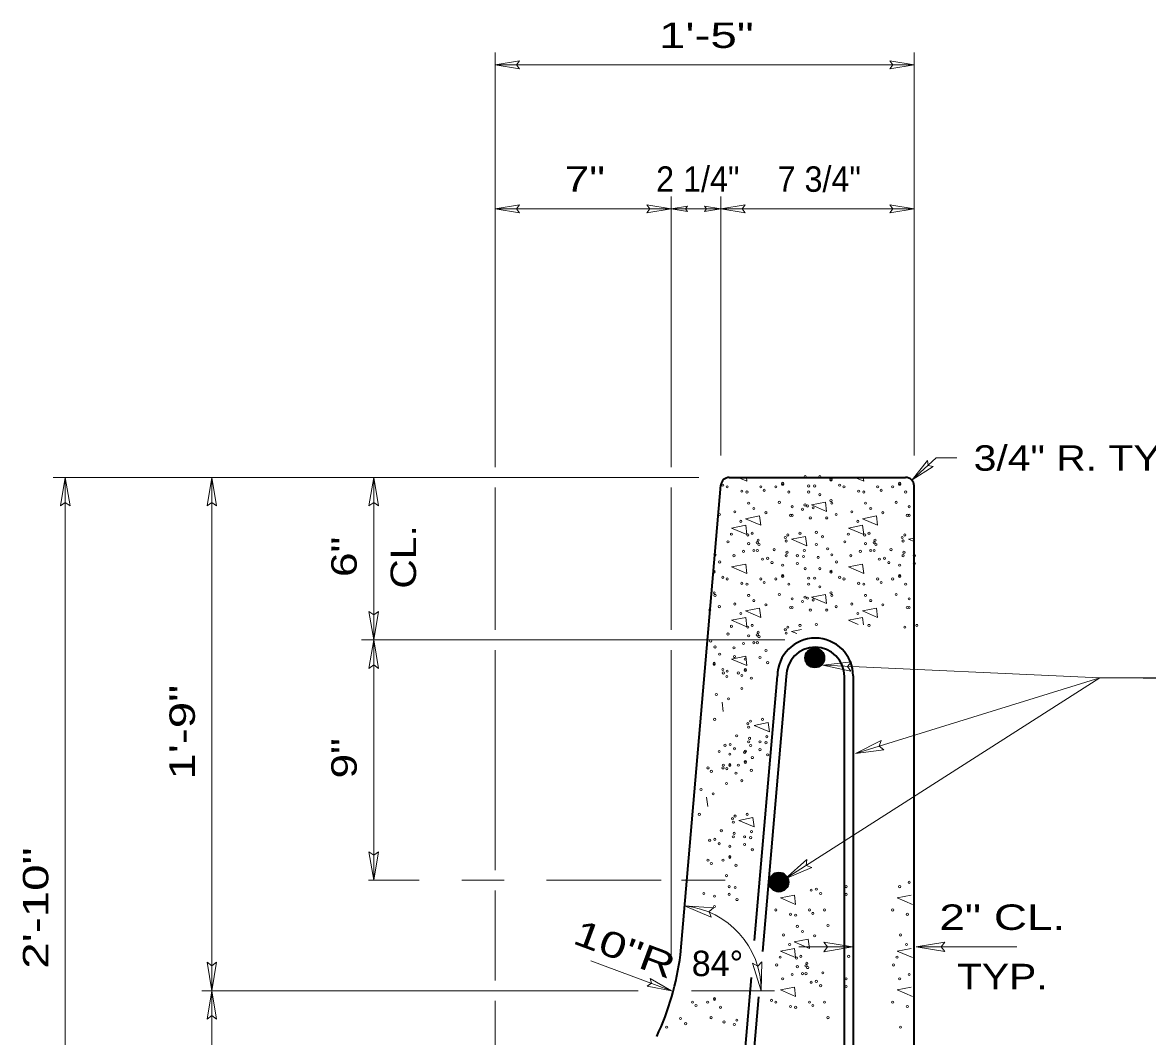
# Model space of a CAD drawing. Extents: x 2.21 to 9.21, y 11.59 to 21.05.
# Drawn here: x 2.823 to 5.477, y 18.662 to 21.053 of the extents above; entities that cross this region are included whole.
import ezdxf
from ezdxf.enums import TextEntityAlignment as Align

# ---------------------------------------------------------------- set-up
doc = ezdxf.new("R2010")
doc.units = 0
doc.header["$LTSCALE"] = 0.024
doc.linetypes.add('DOT_DASHED', pattern=[7.7, 5, -1.2, 0.3, -1.2])
for name, color, linetype, lineweight in [('1', 7, 'Continuous', 35), ('10', 7, 'Continuous', 13), ('12', 7, 'Continuous', 53), ('6', 7, 'Continuous', 13)]:
    doc.layers.add(name, color=color, linetype=linetype, lineweight=lineweight)

msp = doc.modelspace()

# ---------------------------------------------------------------- linework, layer by layer
at = {"layer": '1'}
for p, q in [((4.3755, 18.85467), (4.47067, 19.962)), ((4.49067, 19.98033), (4.9065, 19.98033)), ((4.92667, 17.90333), (4.92667, 19.96033)), ((4.55033, 18.88833), (4.604, 19.512)), ((4.62467, 19.51117), (4.56883, 18.86217))]:
    msp.add_line(p, q, dxfattribs=at)
for points in [[(4.78283, 19.512), (4.78283, 17.57083), (4.78283, 17.57), (4.76217, 17.57), (4.76217, 19.51117)], [(4.5595, 18.755), (4.48883, 17.93367), (4.48883, 17.56383), (4.48883, 17.5645), (4.46833, 17.5645), (4.46833, 17.93417), (4.54283, 18.80083)]]:
    msp.add_lwpolyline(points, dxfattribs=at)
for centre, radius in [((4.69223, 19.55451), 0.02253), ((4.69204, 19.5547), 0.02103), ((4.69002, 19.5547), 0.01823), ((4.69229, 19.55417), 0.02028), ((4.69289, 19.55321), 0.01988), ((4.69278, 19.55392), 0.0185), ((4.69076, 19.55559), 0.01508), ((4.69328, 19.55381), 0.01751), ((4.69342, 19.55332), 0.0166), ((4.69041, 19.55381), 0.01309), ((4.69367, 19.55307), 0.01584), ((4.69342, 19.55268), 0.0151), ((4.68927, 19.55307), 0.01045), ((4.69381, 19.55268), 0.01471), ((4.69353, 19.55293), 0.01421), ((4.69416, 19.55257), 0.01358), ((4.6943, 19.55282), 0.01272), ((4.69441, 19.55296), 0.01184), ((4.69101, 19.55357), 0.00844), ((4.69441, 19.55321), 0.01085), ((4.69455, 19.55293), 0.01021), ((4.69455, 19.55282), 0.00921), ((4.69494, 19.55204), 0.00882), ((4.69516, 19.55194), 0.00805), ((4.69516, 19.55215), 0.00706), ((4.69544, 19.55233), 0.00681), ((4.69544, 19.55169), 0.00627), ((4.69569, 19.55218), 0.00602), ((4.69579, 19.55204), 0.00515), ((4.69544, 19.55243), 0.0043), ((4.69594, 19.5519), 0.00382), ((4.69608, 19.55194), 0.00316), ((4.69632, 19.55179), 0.00241), ((4.69632, 19.55204), 0.00213), ((4.69707, 19.55194), 0.00267), ((4.69629, 19.55204), 0.00139), ((4.69604, 19.55204), 0.000653), ((4.69657, 19.55204), 0.000415), ((4.60766, 19.02591), 0.02253), ((4.60746, 19.0261), 0.02103), ((4.60544, 19.0261), 0.01823), ((4.60771, 19.02556), 0.02028), ((4.60831, 19.02461), 0.01988), ((4.60821, 19.02532), 0.0185), ((4.60619, 19.02698), 0.01508), ((4.6087, 19.02521), 0.01751), ((4.60885, 19.02471), 0.0166), ((4.60583, 19.02521), 0.01309), ((4.60909, 19.02447), 0.01584), ((4.60885, 19.02408), 0.0151), ((4.6047, 19.02447), 0.01045), ((4.60924, 19.02408), 0.01471), ((4.60895, 19.02432), 0.01421), ((4.60959, 19.02397), 0.01358), ((4.60973, 19.02422), 0.01272), ((4.60984, 19.02436), 0.01184), ((4.60644, 19.02496), 0.00844), ((4.60984, 19.02461), 0.01085), ((4.60998, 19.02432), 0.01021), ((4.60998, 19.02422), 0.00921), ((4.61037, 19.02344), 0.00882), ((4.61058, 19.02333), 0.00805), ((4.61058, 19.02354), 0.00706), ((4.61087, 19.02372), 0.00681), ((4.61087, 19.02308), 0.00627), ((4.61111, 19.02358), 0.00602), ((4.61122, 19.02344), 0.00515), ((4.61087, 19.02383), 0.0043), ((4.61136, 19.0233), 0.00382), ((4.6115, 19.02333), 0.00316), ((4.61175, 19.02319), 0.00241), ((4.61175, 19.02344), 0.00213), ((4.6125, 19.02333), 0.00267), ((4.61172, 19.02344), 0.00139), ((4.61147, 19.02344), 0.000653), ((4.612, 19.02344), 0.000415)]:
    msp.add_circle(centre, radius, dxfattribs=at)
for centre, radius, start, end in [((4.49063, 19.96026), 0.02, 90, 175.08387), ((4.90658, 19.96026), 0.02, 0, 90), ((4.69339, 19.512), 0.08937, 0, 180), ((4.69339, 19.51114), 0.06877, 0, 180), ((3.72781, 18.93854), 0.65305, 334.93556, 352.62166)]:
    msp.add_arc(centre, radius, start, end, dxfattribs=at)
at = {"layer": '10'}
for p, q in [((3.938, 20.00433), (3.938, 20.982)), ((4.92667, 20.03233), (4.92667, 20.982)), ((3.99567, 20.96267), (3.938, 20.95317)), ((3.938, 20.95317), (4.92667, 20.95317)), ((3.99567, 20.9435), (3.938, 20.95317)), ((3.99567, 20.96267), (3.9885, 20.95317)), ((3.99567, 20.9435), (3.9885, 20.95317)), ((4.869, 20.96267), (4.92667, 20.95317)), ((4.869, 20.96267), (4.87617, 20.95317)), ((4.869, 20.9435), (4.92667, 20.95317)), ((4.869, 20.9435), (4.87617, 20.95317)), ((3.99567, 20.6235), (3.938, 20.61383)), ((3.99567, 20.6235), (3.9885, 20.61383)), ((4.29583, 20.6235), (4.3535, 20.61383)), ((4.29583, 20.6235), (4.303, 20.61383)), ((4.3535, 20.64267), (4.3535, 20.00433)), ((4.47067, 20.03233), (4.47067, 20.64267)), ((4.52833, 20.6235), (4.47067, 20.61383)), ((4.52833, 20.6235), (4.52117, 20.61383)), ((4.869, 20.6235), (4.92667, 20.61383)), ((4.869, 20.6235), (4.87617, 20.61383)), ((3.99567, 20.60417), (3.938, 20.61383)), ((3.99567, 20.60417), (3.9885, 20.61383)), ((4.29583, 20.60417), (4.3535, 20.61383)), ((4.29583, 20.60417), (4.303, 20.61383)), ((4.39183, 20.62017), (4.3535, 20.61383)), ((4.39183, 20.6075), (4.3535, 20.61383)), ((4.39183, 20.62017), (4.387, 20.61383)), ((4.39183, 20.6075), (4.387, 20.61383)), ((4.43233, 20.62017), (4.47067, 20.61383)), ((4.43233, 20.62017), (4.43717, 20.61383)), ((4.43233, 20.6075), (4.47067, 20.61383)), ((4.43233, 20.6075), (4.43717, 20.61383)), ((4.52833, 20.60417), (4.47067, 20.61383)), ((4.52833, 20.60417), (4.52117, 20.61383)), ((4.869, 20.60417), (4.92667, 20.61383)), ((4.869, 20.60417), (4.87617, 20.61383)), ((4.95833, 20.02033), (4.92217, 19.9745)), ((4.95833, 20.02033), (4.9595, 20.00833)), ((4.97133, 20.00617), (4.92217, 19.9745)), ((4.97133, 20.00617), (4.9595, 20.00833)), ((4.41867, 19.98033), (2.89533, 19.98033)), ((2.91283, 19.913), (2.924, 19.98033)), ((2.924, 17.9405), (2.924, 19.98033)), ((2.93533, 19.913), (2.924, 19.98033)), ((3.25867, 19.913), (3.26983, 19.98033)), ((3.281, 19.913), (3.26983, 19.98033)), ((3.26983, 18.76983), (3.26983, 19.98033)), ((3.6405, 19.913), (3.65167, 19.98033)), ((3.66283, 19.913), (3.65167, 19.98033)), ((3.65167, 19.59717), (3.65167, 19.98033)), ((3.938, 19.62117), (3.938, 19.95633)), ((4.3535, 19.95633), (4.3535, 19.62117)), ((2.91283, 19.913), (2.924, 19.9215)), ((2.93533, 19.913), (2.924, 19.9215)), ((3.25867, 19.913), (3.26983, 19.9215)), ((3.281, 19.913), (3.26983, 19.9215)), ((3.6405, 19.913), (3.65167, 19.9215)), ((3.66283, 19.913), (3.65167, 19.9215)), ((3.6405, 19.66433), (3.65167, 19.59717)), ((3.6405, 19.66433), (3.65167, 19.656)), ((3.66283, 19.66433), (3.65167, 19.59717)), ((3.66283, 19.66433), (3.65167, 19.656)), ((4.62133, 19.59717), (3.62283, 19.59717)), ((3.6405, 19.53), (3.65167, 19.59717)), ((3.65167, 19.03033), (3.65167, 19.59717)), ((3.66283, 19.53), (3.65167, 19.59717)), ((3.938, 19.05433), (3.938, 19.57317)), ((4.3535, 18.85217), (4.3535, 19.57317)), ((3.6405, 19.53), (3.65167, 19.53833)), ((3.66283, 19.53), (3.65167, 19.53833)), ((4.77867, 19.5455), (4.711, 19.53733)), ((5.36517, 19.5075), (4.711, 19.53733)), ((4.77767, 19.52317), (4.711, 19.53733)), ((4.77867, 19.5455), (4.76983, 19.53467)), ((4.77767, 19.52317), (4.76983, 19.53467)), ((5.36517, 19.5075), (4.62267, 19.03333)), ((5.36517, 19.5075), (4.788, 19.329)), ((5.46717, 19.5075), (5.36517, 19.5075)), ((4.84883, 19.35967), (4.788, 19.329)), ((4.84883, 19.35967), (4.84417, 19.3465)), ((4.8555, 19.33817), (4.788, 19.329)), ((4.8555, 19.33817), (4.84417, 19.3465)), ((3.6405, 19.0975), (3.65167, 19.03033)), ((3.6405, 19.0975), (3.65167, 19.08917)), ((3.66283, 19.0975), (3.65167, 19.03033)), ((3.66283, 19.0975), (3.65167, 19.08917)), ((4.67333, 19.079), (4.62267, 19.03333)), ((4.68533, 19.06017), (4.62267, 19.03333)), ((4.67333, 19.079), (4.67233, 19.065)), ((4.68533, 19.06017), (4.67233, 19.065)), ((3.938, 18.79383), (3.938, 19.00633)), ((4.17933, 19.03033), (4.3295, 19.03033)), ((4.4805, 19.03033), (4.3775, 19.03033)), ((4.44817, 18.94333), (4.38533, 18.96983)), ((4.45367, 18.965), (4.38533, 18.96983)), ((4.45367, 18.965), (4.44317, 18.95633)), ((4.44817, 18.94333), (4.44317, 18.95633)), ((4.65483, 18.873), (4.781, 18.873)), ((4.71383, 18.88433), (4.781, 18.873)), ((4.71383, 18.88433), (4.72233, 18.873)), ((4.71383, 18.86183), (4.781, 18.873)), ((4.71383, 18.86183), (4.72233, 18.873)), ((4.999, 18.8845), (4.93183, 18.87333)), ((5.16917, 18.87333), (4.93183, 18.87333)), ((4.999, 18.86217), (4.93183, 18.87333)), ((4.999, 18.8845), (4.99067, 18.87333)), ((4.999, 18.86217), (4.99067, 18.87333)), ((3.25867, 18.837), (3.26983, 18.76983)), ((3.25867, 18.837), (3.26983, 18.82867)), ((3.281, 18.837), (3.26983, 18.76983)), ((3.281, 18.837), (3.26983, 18.82867)), ((4.35433, 18.76983), (4.164, 18.8405)), ((4.54533, 18.83483), (4.56583, 18.76983)), ((4.54533, 18.83483), (4.55767, 18.828)), ((4.5675, 18.838), (4.55767, 18.828)), ((4.5675, 18.838), (4.56583, 18.76983)), ((4.30367, 18.79883), (4.35433, 18.76983)), ((4.30367, 18.79883), (4.30717, 18.78733)), ((4.276, 18.76983), (3.24583, 18.76983)), ((3.25867, 18.7025), (3.26983, 18.76983)), ((3.281, 18.7025), (3.26983, 18.76983)), ((4.297, 18.78083), (4.30717, 18.78733)), ((4.297, 18.78083), (4.35433, 18.76983)), ((4.40133, 18.76983), (4.59733, 18.76983)), ((3.938, 18.17917), (3.938, 18.74583)), ((3.25867, 18.7025), (3.26983, 18.711)), ((3.281, 18.7025), (3.26983, 18.711))]:
    msp.add_line(p, q, dxfattribs=at)
at = {"layer": '10', "lineweight": 25}
msp.add_line((5.46717, 19.5075), (6.30483, 19.5075), dxfattribs=at)
at = {"layer": '10', "linetype": 'DOT_DASHED'}
msp.add_line((4.17933, 19.03033), (3.62283, 19.03033), dxfattribs=at)
at = {"layer": '10'}
for points in [[(3.938, 20.61383), (4.3535, 20.61383), (4.47067, 20.61383), (4.92667, 20.61383)], [(5.02733, 20.02617), (4.979, 20.02617), (4.92217, 19.9745)], [(3.26983, 17.9405), (3.26983, 18.11817), (3.26983, 18.76983)]]:
    msp.add_lwpolyline(points, dxfattribs=at)
msp.add_arc((4.36536, 18.77036), 0.20043, 359.83506, 84.27453, dxfattribs=at)
at = {"layer": '6'}
for p, q in [((4.9135, 19.8345), (4.92833, 19.83733)), ((4.9285, 19.828), (4.9135, 19.8345)), ((4.79483, 19.63383), (4.772, 19.64367)), ((4.63767, 19.61717), (4.66117, 19.62183)), ((4.64983, 19.612), (4.63767, 19.61717)), ((4.4735, 19.45033), (4.47633, 19.4285)), ((4.43717, 19.2265), (4.44017, 19.2045)), ((4.88683, 18.98883), (4.92, 18.99533)), ((4.92283, 18.9735), (4.88683, 18.98883)), ((4.88683, 18.86317), (4.92, 18.86967)), ((4.92283, 18.84783), (4.88683, 18.86317)), ((4.88683, 18.7715), (4.92, 18.778)), ((4.92283, 18.75617), (4.88683, 18.7715))]:
    msp.add_line(p, q, dxfattribs=at)
for points in [[(4.531, 19.98033), (4.53217, 19.97133), (4.51117, 19.98033)], [(4.80683, 19.98033), (4.808, 19.97133), (4.787, 19.98033)], [(4.772, 19.64367), (4.80517, 19.65017), (4.80733, 19.63283)]]:
    msp.add_lwpolyline(points, dxfattribs=at)
for points in [[(4.6845, 19.9155), (4.7175, 19.922), (4.72033, 19.9)], [(4.52883, 19.88283), (4.56183, 19.88933), (4.56467, 19.8675)], [(4.8045, 19.88283), (4.83767, 19.88933), (4.8405, 19.8675)], [(4.49617, 19.861), (4.52933, 19.8675), (4.53217, 19.8455)], [(4.772, 19.861), (4.80517, 19.8675), (4.808, 19.8455)], [(4.63767, 19.8345), (4.67067, 19.841), (4.67367, 19.819)], [(4.49617, 19.76933), (4.52933, 19.77583), (4.53217, 19.754)], [(4.772, 19.76933), (4.80517, 19.77583), (4.808, 19.754)], [(4.6845, 19.69817), (4.7175, 19.7045), (4.72033, 19.68267)], [(4.52883, 19.6655), (4.56183, 19.672), (4.56467, 19.65017)], [(4.8045, 19.6655), (4.83767, 19.672), (4.8405, 19.65017)], [(4.49617, 19.64367), (4.52933, 19.65017), (4.53217, 19.62817)], [(4.49617, 19.552), (4.52933, 19.5585), (4.53217, 19.53667)], [(4.54933, 19.3955), (4.58233, 19.402), (4.58517, 19.38)], [(4.513, 19.1715), (4.54617, 19.178), (4.549, 19.15617)], [(4.61117, 18.98883), (4.64417, 18.99533), (4.647, 18.9735)], [(4.64367, 18.885), (4.67667, 18.8915), (4.67967, 18.86967)], [(4.61117, 18.86317), (4.64417, 18.86967), (4.647, 18.84783)], [(4.61117, 18.7715), (4.64417, 18.778), (4.647, 18.75617)]]:
    msp.add_lwpolyline(points, close=True, dxfattribs=at)
for centre in [(4.47523, 19.96214), (4.48543, 19.9581), (4.56485, 19.9581), (4.60041, 19.9581), (4.61669, 19.96622), (4.61669, 19.96418), (4.66962, 19.9825), (4.67774, 19.96014), (4.69203, 19.96014), (4.70423, 19.9825), (4.73071, 19.97642), (4.73071, 19.97438), (4.75104, 19.96214), (4.76124, 19.9581), (4.84065, 19.9581), (4.87622, 19.9581), (4.8925, 19.96622), (4.8925, 19.96418), (4.52004, 19.94789), (4.53224, 19.94585), (4.57297, 19.94993), (4.63094, 19.94585), (4.67774, 19.94585), (4.70423, 19.93977), (4.79584, 19.94789), (4.80805, 19.94585), (4.84877, 19.94993), (4.90674, 19.94585), (4.53632, 19.91941), (4.54852, 19.90717), (4.60853, 19.92145), (4.63906, 19.91125), (4.6635, 19.90517), (4.66938, 19.91541), (4.67502, 19.91297), (4.68867, 19.90861), (4.73071, 19.92549), (4.73271, 19.91941), (4.81213, 19.91941), (4.82433, 19.90717), (4.88434, 19.92145), (4.91486, 19.91125), (4.46711, 19.89292), (4.50376, 19.89905), (4.57705, 19.89701), (4.63502, 19.89088), (4.63906, 19.89088), (4.68183, 19.8848), (4.72051, 19.8848), (4.74291, 19.89292), (4.77956, 19.89905), (4.85285, 19.89701), (4.91082, 19.89088), (4.91486, 19.89088), (4.518, 19.87664), (4.7938, 19.87664), (4.48747, 19.82827), (4.4956, 19.8466), (4.53428, 19.84456), (4.54448, 19.84864), (4.55669, 19.82623), (4.55873, 19.83235), (4.62278, 19.83844), (4.62482, 19.83031), (4.6289, 19.84456), (4.65738, 19.84864), (4.69607, 19.85068), (4.71035, 19.84048), (4.76328, 19.82827), (4.7714, 19.8466), (4.81009, 19.84456), (4.82029, 19.84864), (4.83249, 19.82623), (4.83453, 19.83235), (4.89858, 19.83844), (4.90062, 19.83031), (4.9047, 19.84456), (4.45691, 19.79775), (4.52412, 19.80587), (4.53632, 19.82419), (4.54852, 19.80791), (4.55669, 19.80791), (4.56077, 19.82215), (4.59633, 19.80995), (4.62686, 19.80383), (4.66758, 19.80791), (4.69607, 19.82215), (4.72255, 19.81199), (4.73271, 19.79775), (4.79992, 19.80587), (4.81213, 19.82419), (4.82433, 19.80791), (4.83249, 19.80791), (4.83657, 19.82215), (4.87214, 19.80995), (4.90266, 19.80383), (4.46783, 19.78083), (4.50172, 19.79571), (4.56889, 19.78755), (4.58113, 19.78959), (4.59129, 19.77943), (4.61669, 19.77331), (4.62482, 19.79571), (4.6513, 19.79571), (4.6513, 19.77739), (4.66554, 19.79367), (4.70015, 19.79163), (4.74364, 19.78083), (4.77752, 19.79571), (4.84469, 19.78755), (4.85693, 19.78959), (4.86709, 19.77943), (4.8925, 19.77331), (4.90062, 19.79571), (4.9271, 19.79571), (4.9271, 19.77739), (4.45491, 19.75906), (4.45491, 19.75702), (4.47523, 19.74478), (4.61669, 19.74886), (4.61669, 19.74682), (4.66962, 19.76514), (4.70423, 19.76514), (4.73071, 19.75906), (4.73071, 19.75702), (4.75104, 19.74478), (4.8925, 19.74886), (4.8925, 19.74682), (4.48543, 19.74074), (4.52004, 19.73054), (4.53224, 19.7285), (4.56485, 19.74074), (4.57297, 19.73258), (4.60041, 19.74074), (4.63094, 19.7285), (4.67774, 19.74278), (4.67774, 19.7285), (4.69203, 19.74278), (4.70423, 19.72242), (4.76124, 19.74074), (4.79584, 19.73054), (4.80805, 19.7285), (4.84065, 19.74074), (4.84877, 19.73258), (4.87622, 19.74074), (4.90674, 19.7285), (4.45491, 19.70814), (4.45691, 19.70205), (4.53632, 19.70205), (4.60853, 19.70409), (4.63906, 19.69389), (4.66938, 19.69805), (4.67502, 19.69561), (4.73071, 19.70814), (4.73271, 19.70205), (4.81213, 19.70205), (4.88434, 19.70409), (4.91486, 19.69389), (4.44471, 19.66745), (4.46711, 19.67557), (4.50376, 19.68169), (4.54852, 19.68981), (4.57705, 19.67965), (4.63502, 19.67353), (4.63906, 19.67353), (4.6635, 19.68781), (4.68183, 19.66745), (4.68867, 19.69125), (4.72051, 19.66745), (4.74291, 19.67557), (4.77956, 19.68169), (4.82433, 19.68981), (4.85285, 19.67965), (4.91082, 19.67353), (4.91486, 19.67353), (4.518, 19.65929), (4.7938, 19.65929), (4.4956, 19.62924), (4.53428, 19.6272), (4.54448, 19.63128), (4.55873, 19.615), (4.62278, 19.62108), (4.62482, 19.61296), (4.6289, 19.6272), (4.65738, 19.63128), (4.69607, 19.63332), (4.82029, 19.63128), (4.9047, 19.6272), (4.93319, 19.63128), (4.44675, 19.59464), (4.48747, 19.61092), (4.52412, 19.58852), (4.53632, 19.60684), (4.54852, 19.59056), (4.55669, 19.60888), (4.55669, 19.59056), (4.56077, 19.6048), (4.45691, 19.58039), (4.46783, 19.56347), (4.50172, 19.57835), (4.57721, 19.57203), (4.45491, 19.54171), (4.45491, 19.53967), (4.50296, 19.55779), (4.52836, 19.55167), (4.56297, 19.55575), (4.58129, 19.54351), (4.47523, 19.52743), (4.47651, 19.5191), (4.48463, 19.51094), (4.48543, 19.52339), (4.51208, 19.5191), (4.52004, 19.51318), (4.52836, 19.52723), (4.52836, 19.52519), (4.5426, 19.50686), (4.5202, 19.48246), (4.46019, 19.46818), (4.48871, 19.45802), (4.45615, 19.40965), (4.54056, 19.40557), (4.56905, 19.40965), (4.53444, 19.39945), (4.53648, 19.39132), (4.48055, 19.34856), (4.49279, 19.3506), (4.508, 19.37096), (4.53648, 19.35672), (4.53852, 19.36484), (4.54092, 19.34812), (4.56297, 19.35672), (4.57721, 19.35468), (4.57925, 19.36892), (4.46667, 19.33388), (4.49207, 19.32775), (4.50296, 19.34044), (4.52668, 19.33183), (4.52836, 19.33432), (4.56297, 19.3384), (4.58129, 19.32615), (4.44023, 19.29519), (4.47579, 19.29519), (4.47651, 19.30175), (4.48463, 19.29359), (4.49207, 19.30331), (4.49207, 19.30127), (4.51208, 19.30175), (4.52836, 19.30987), (4.52836, 19.30783), (4.545, 19.31959), (4.44835, 19.28703), (4.50632, 19.28295), (4.5426, 19.28951), (4.4239, 19.24426), (4.48391, 19.25854), (4.5202, 19.2651), (4.45243, 19.2341), (4.41986, 19.18573), (4.49816, 19.17553), (4.5002, 19.16741), (4.50428, 19.18165), (4.53276, 19.18573), (4.47171, 19.14705), (4.50224, 19.14092), (4.54296, 19.145), (4.44427, 19.12464), (4.45651, 19.12668), (4.46667, 19.11652), (4.49207, 19.1104), (4.5002, 19.1328), (4.52668, 19.1328), (4.52668, 19.11448), (4.54092, 19.13076), (4.49207, 19.08596), (4.49207, 19.08392), (4.545, 19.10224), (4.44023, 19.07783), (4.44835, 19.06967), (4.47579, 19.07783), (4.50632, 19.06559), (4.48391, 19.04119), (4.49039, 19.01526), (4.50464, 19.01322), (4.68379, 19.0071), (4.69603, 19.00914), (4.7662, 19.01526), (4.89242, 19.01526), (4.91482, 19.02543), (4.43038, 18.99898), (4.45579, 18.99286), (4.49039, 18.99694), (4.50872, 18.9847), (4.70619, 18.99898), (4.7662, 18.99694), (4.45579, 18.96842), (4.60033, 18.9603), (4.63494, 18.95009), (4.67974, 18.9603), (4.68787, 18.95213), (4.71531, 18.9603), (4.87614, 18.9603), (4.91074, 18.95009), (4.64714, 18.94805), (4.72343, 18.92365), (4.61866, 18.90125), (4.65122, 18.92161), (4.66342, 18.90937), (4.69195, 18.89921), (4.89446, 18.90125), (4.6329, 18.87884), (4.9087, 18.87884), (4.61049, 18.8488), (4.64918, 18.84676), (4.65938, 18.85084), (4.77228, 18.85084), (4.8863, 18.8488), (4.60237, 18.83047), (4.65122, 18.82639), (4.67158, 18.82843), (4.67362, 18.83456), (4.67566, 18.82435), (4.87818, 18.83047), (4.61661, 18.79791), (4.63902, 18.80807), (4.66342, 18.81011), (4.67158, 18.81011), (4.68379, 18.78975), (4.69603, 18.79179), (4.71123, 18.81215), (4.7662, 18.79791), (4.89242, 18.79791), (4.91482, 18.80807), (4.70619, 18.78163), (4.7662, 18.77959), (4.40394, 18.74294), (4.43951, 18.74294), (4.45579, 18.75106), (4.45579, 18.74902), (4.59013, 18.74698), (4.60033, 18.74294), (4.67974, 18.74294), (4.71531, 18.74294), (4.87614, 18.74294), (4.41206, 18.73478), (4.47003, 18.7307), (4.63494, 18.73274), (4.64714, 18.7307), (4.68787, 18.73478), (4.91074, 18.73274), (4.34285, 18.68389), (4.37542, 18.70425), (4.38762, 18.69201), (4.44763, 18.70629), (4.47815, 18.69609), (4.5026, 18.69001), (4.50848, 18.70025), (4.72343, 18.70629), (4.89446, 18.68389)]:
    msp.add_circle(centre, 0.00252, dxfattribs=at)

# ---------------------------------------------------------------- texts
at = {"layer": '12'}
for s, width, p in [('1\'-5"', 1.4, (4.4365, 20.99308)), ('7"', 1.3, (4.14987, 20.65383)), ('2 1/4"', 0.95, (4.41629, 20.65383)), ('7 3/4"', 0.95, (4.70279, 20.65383)), ('2" CL.', 1.35, (5.13471, 18.91325)), ('TYP.', 1.2, (5.13471, 18.77325))]:
    msp.add_text(s, height=0.06001, dxfattribs=dict(at, width=width)).set_placement(p, align=Align.CENTER)
at = {"layer": '12', "width": 1.2}
msp.add_text('3/4" R. TYP.', height=0.06001, dxfattribs=at).set_placement((5.06725, 19.99608))
at = {"layer": '12'}
for s, rotation, width, p in [('CL.', 90, 1.2, (3.75158, 19.79283)), ('6"', 90, 1.3, (3.61158, 19.79287)), ('1\'-9"', 90, 1.4, (3.22983, 19.37925)), ('9"', 90, 1.3, (3.61158, 19.31788)), ('2\'-10"', 90, 1.4, (2.884, 18.96458)), ('10"R', 339.641, 1.4, (4.23348, 18.83968))]:
    msp.add_text(s, height=0.06001, rotation=rotation, dxfattribs=dict(at, width=width)).set_placement(p, align=Align.CENTER)
msp.add_text('84°', height=0.06001, dxfattribs=at).set_placement((4.46275, 18.80417), align=Align.CENTER)

doc.saveas('drawing.dxf')
